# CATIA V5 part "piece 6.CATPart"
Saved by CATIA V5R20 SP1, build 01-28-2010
Part number: piece 6
Bounding box of the stored display mesh (mm): x -20 to 120, y -20 to 120, z 0 to 10
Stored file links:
  D:\Dropbox\IAO_2011\MMS_GR1\jdubreuilr\jdubreuilr\jdubreuilr\piece 6.CATPart
  C:\Users\Jean-Philippe\Desktop\projet IAO\assemblage\piece 6 g.CATPart
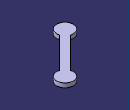
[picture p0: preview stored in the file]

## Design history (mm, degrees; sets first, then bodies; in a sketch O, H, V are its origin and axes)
Set1
  Point1: type OnPlane, Support xy-plane, H 0, V 0, Direction (1, 0, 0)
  Point2: type OnPlane, Support xy-plane, H 100, V 100, Direction (1, 0, 0)
  Line1: type Normal, RefPoint Point1, RefSkin end face of Pad1, Start 0, End 20
  Line2: type Normal, RefPoint Point2, RefSkin end face of Pad1, Start 0, End 20
Body1 (main body)
  Sketch1 on xy-plane, origin (0, 0, 0), H (1, 0, 0), V (0, 1, 0)
    arc A1 centre (0, 0) radius 20 from (5.1764, 19.3185) to (19.3185, 5.1764) ccw
    arc A2 centre (100, 100) radius 20 from (94.8236, 80.6815) to (80.6815, 94.8236) ccw
    point P3 (100, 100)
    point P5 (94.8236, 80.6815)
    reference projected point E1 (100, 100)
    line L1 (80.6815, 94.8236) -> (5.1764, 19.3185)
    line L2 (94.8236, 80.6815) -> (19.3185, 5.1764)
    point P6 (94.8236, 80.6815)
    axis line L3 (100, 100) -> (0, 0)
    radius A1 = 20
    radius A2 = 20
    distance L1 L3 = 10
    distance L2 L3 = 10
    coincidence: P3 E1, P6 A2, P5 P6
  Pad1: profile Sketch1, direction (0, 0, 1), length 10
